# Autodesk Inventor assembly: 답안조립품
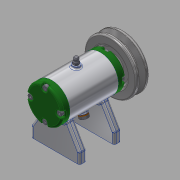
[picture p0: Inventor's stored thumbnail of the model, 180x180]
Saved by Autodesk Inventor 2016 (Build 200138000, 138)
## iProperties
Created: 2018-05
Part Number: 답안조립품
Material: 일반
Document SubType Name: Assembly
Designer: 605-15
Author: 605-15
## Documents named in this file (16)
- C:\Users\605-15\Desktop\480507V1015\답안조립품.iam
- C:\Users\605-15\Desktop\480507V1015\1.본체.ipt
- C:\Users\605-15\Desktop\480507V1015\V벨트풀리.ipt
- C:\Users\605-15\Desktop\480507V1015\너트 M8.ipt
- C:\Users\605-15\Desktop\480507V1015\니플 M6x0.75.ipt
- C:\Users\605-15\Desktop\480507V1015\뒤커버.ipt
- C:\Users\605-15\Desktop\480507V1015\베어링 6002.ipt
- C:\Users\605-15\Desktop\480507V1015\볼트 M4x12.ipt
- C:\Users\605-15\Desktop\480507V1015\볼트 M6x8.ipt
- C:\Users\605-15\Desktop\480507V1015\스프링와셔 8.ipt
- C:\Users\605-15\Desktop\480507V1015\앞커버.ipt
- C:\Users\605-15\Desktop\480507V1015\오일 실 15 25 7.ipt
- C:\Users\605-15\Desktop\480507V1015\와셔 6x11.5.ipt
- C:\Users\605-15\Desktop\480507V1015\와셔 8x17.ipt
- C:\Users\605-15\Desktop\480507V1015\축.ipt
- C:\Users\605-15\Desktop\480507V1015\키 3x3x12.ipt
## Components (2 placed, 2 different names)
1. 1.본체:1
2. V벨트풀리:1 — 각도:1
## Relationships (1: Angle 1)
- 각도:1 [Angle]: V벨트풀리:1
